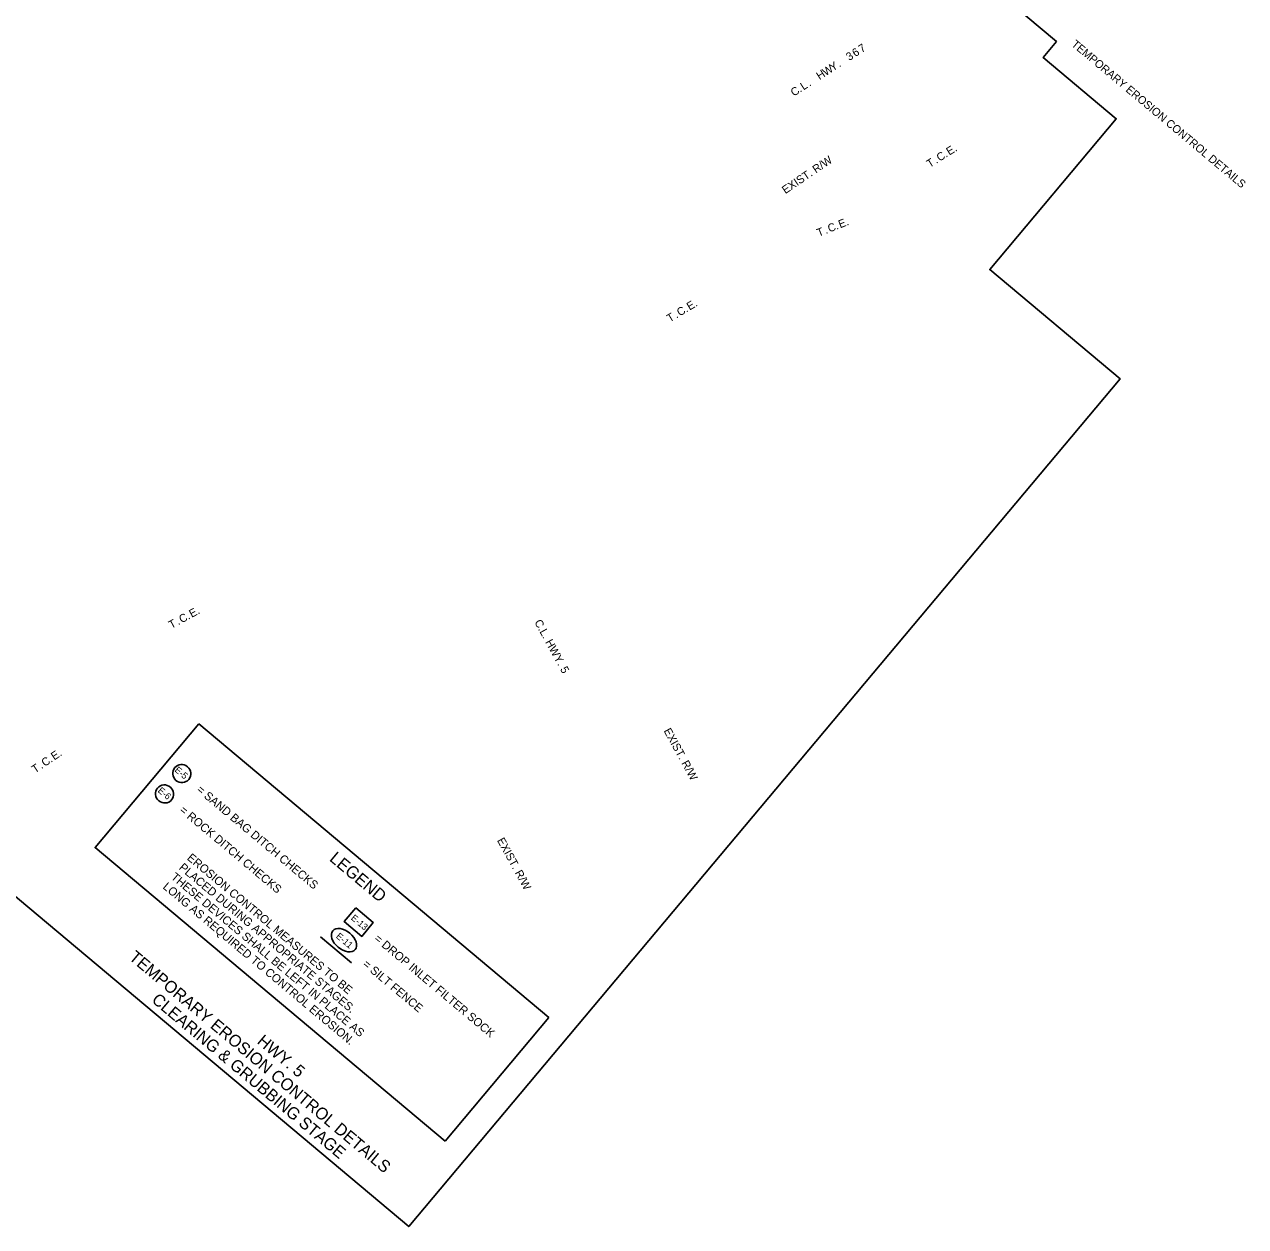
# Model space of a CAD drawing. Extents: x 1292584 to 1294434, y 222754 to 224578.
# Drawn here: x 1293518 to 1294434, y 222754 to 223656 of the extents above; entities that cross this region are included whole.
import ezdxf

# ---------------------------------------------------------------- set-up
doc = ezdxf.new("R2010")
doc.units = 0
for name, color, linetype in [('44', 7, 'Continuous'), ('R_Annotation_Slope', 7, 'Continuous'), ('R_Grid_Sta', 7, 'Continuous'), ('R_ROW', 7, 'Continuous'), ('R_Striping', 7, 'Continuous'), ('S_TREE', 7, 'Continuous')]:
    doc.layers.add(name, color=color, linetype=linetype)

msp = doc.modelspace()

# ---------------------------------------------------------------- linework, layer by layer
for p, q in [((1293911.34, 222911.05), (1293648.85, 223131.31)), ((1293833.53, 222818.32), (1293911.34, 222911.05))]:
    msp.add_line(p, q)
msp.add_lwpolyline([(1293648.85, 223131.31), (1293571.04, 223038.57), (1293833.53, 222818.32)])
at = {"layer": '44'}
msp.add_lwpolyline([(1292584.05, 223779.83), (1293254.04, 224578.3), (1294171.77, 223808.23), (1294139.92, 223770.28), (1294291.79, 223642.84), (1294281.83, 223630.97), (1294336.68, 223584.95), (1294241.87, 223471.95), (1294339.54, 223390), (1293806.17, 222754.35)], close=True, dxfattribs=at)
at = {"layer": 'R_Grid_Sta'}
msp.add_lwpolyline([(1293766.52, 222993.26), (1293779.63, 222982.25), (1293771.01, 222971.97), (1293757.89, 222982.98)], close=True, dxfattribs=at)
for centre, major_axis, ratio in [((1293635.98, 223094.03), (-5.27, 4.42), 0.97521), ((1293623.13, 223078.71), (-5.27, 4.42), 0.97521), ((1293757.64, 222969.05), (8.39, -7.04), 0.622952)]:
    msp.add_ellipse(centre, major_axis=major_axis, ratio=ratio, dxfattribs=at)
at = {"layer": 'S_TREE'}
msp.add_lwpolyline([(1293740.1, 222971.59), (1293763.18, 222952.23)], dxfattribs=at)

# ---------------------------------------------------------------- texts
at = {"layer": 'R_Annotation_Slope'}
for s, p in [('TEMPORARY EROSION CONTROL DETAILS', (1293595.79, 222955.14)), ('CLEARING & GRUBBING STAGE', (1293612.79, 222923.25)), ('HWY. 5', (1293691.82, 222892.19))]:
    msp.add_text(s, height=9, rotation=320, dxfattribs=at).set_placement(p)
at = {"layer": 'R_Grid_Sta'}
for s, height, p in [('E-5 ', 4.876, (1293630.24, 223095.96)), ('E-6 ', 4.876, (1293617.6, 223080.57)), ('= SAND BAG DITCH CHECKS', 6.25, (1293646.63, 223081.01)), ('= ROCK DITCH CHECKS', 6.25, (1293633.78, 223065.69)), ('PLACED DURING APPROPRIATE STAGES. ', 6.25, (1293633.42, 223022.73)), ('EROSION CONTROL MEASURES TO BE', 6.25, (1293639.47, 223029.94)), ('THESE DEVICES SHALL BE LEFT IN PLACE AS ', 6.25, (1293627.37, 223015.52)), ('LONG AS REQUIRED TO CONTROL EROSION.', 6.25, (1293621.32, 223008.31)), ('E-13', 4.876, (1293762.43, 222985.03)), ('E-11 ', 4.876, (1293751.2, 222971.33)), ('= DROP INLET FILTER SOCK', 6.25, (1293779.79, 222969.28)), ('= SILT FENCE', 6.25, (1293771.11, 222950.21))]:
    msp.add_text(s, height=height, rotation=320.00011, dxfattribs=at).set_placement(p)
at = {"layer": 'R_ROW'}
msp.add_text('EXIST. R/W', height=6, rotation=34.11752, dxfattribs=at).set_placement((1294088.57, 223528.38))
at = {"layer": 'R_Striping'}
for s, rotation, p in [('7', 32.74582, (1294145.78, 223634.22)), ('TEMPORARY EROSION CONTROL DETAILS', 320, (1294302.63, 223640.02)), ('3', 32.74582, (1294136.48, 223628.24)), ('6', 32.74582, (1294141.01, 223631.15)), ('H', 32.74582, (1294114.19, 223613.9)), ('W', 32.74582, (1294118.72, 223616.82)), ('Y', 32.74582, (1294124.12, 223620.29)), ('.', 32.74582, (1294128.97, 223623.41)), ('C', 32.74582, (1294094.92, 223601.51)), ('L', 32.74582, (1294102.15, 223606.16)), ('.', 32.74582, (1294099.69, 223604.58)), ('.', 32.74582, (1294106.68, 223609.07)), ('C', 32.15368, (1294204.26, 223552.73)), ('E', 32.15368, (1294211.54, 223557.3)), ('.', 32.15368, (1294216.1, 223560.17)), ('T', 32.15368, (1294196.82, 223548.05)), ('.', 32.15368, (1294201.78, 223551.17)), ('.', 32.15368, (1294209.06, 223555.74)), ('T', 21.6622, (1294113.56, 223496.39)), ('C', 21.6622, (1294121.72, 223499.64)), ('.', 21.6622, (1294126.99, 223501.73)), ('E', 21.6622, (1294129.72, 223502.81)), ('.', 21.6622, (1294134.72, 223504.8)), ('.', 21.6622, (1294119, 223498.56)), ('E', 30.9348, (1294016.79, 223441.11)), ('T', 30.9348, (1294001.88, 223432.17)), ('C', 30.9348, (1294009.42, 223436.69)), ('.', 30.9348, (1294014.28, 223439.61)), ('.', 30.9348, (1294021.41, 223443.88)), ('.', 30.9348, (1294006.9, 223435.19)), ('T', 28.53219, (1293628.19, 223202.42)), ('C', 28.53219, (1293635.91, 223206.62)), ('.', 28.53219, (1293640.89, 223209.32)), ('E', 28.53219, (1293643.46, 223210.72)), ('.', 28.53219, (1293648.19, 223213.29)), ('.', 28.53219, (1293633.33, 223205.22)), ('C.L. HWY. 5', 298.77322, (1293900.19, 223207.5)), ('EXIST. R/W', 298.77322, (1293997.14, 223126.1)), ('E', 34.00129, (1293540.4, 223103.76)), ('T', 34.00129, (1293525.99, 223094.04)), ('C', 34.00129, (1293533.27, 223098.96)), ('.', 34.00129, (1293537.97, 223102.13)), ('.', 34.00129, (1293544.87, 223106.78)), ('.', 34.00129, (1293530.84, 223097.32)), ('EXIST. R/W', 298.77322, (1293872.22, 223043.94))]:
    msp.add_text(s, height=6, rotation=rotation, dxfattribs=at).set_placement(p)
at = {"layer": 'S_TREE'}
msp.add_text('LEGEND', height=9.143, rotation=320.00011, dxfattribs=at).set_placement((1293746.11, 223029.2))

doc.saveas('drawing.dxf')
